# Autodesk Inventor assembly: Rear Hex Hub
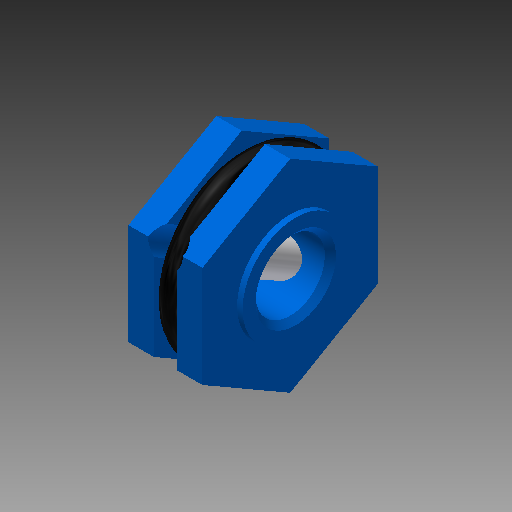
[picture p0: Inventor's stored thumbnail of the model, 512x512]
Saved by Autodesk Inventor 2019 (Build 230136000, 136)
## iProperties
Shininess: 50.0
Compacted: True
Length Units: 11272
Angle Units: 11279
Time Units: 11290
Mass Units: 11286
Length Display Precision: 4
Angle Display Precision: 2
Company: Autodesk
Created: 2000-05
Part Number: Rear Hex Hub
Project: Inventor Samples
User Status: IN PROGRESS
Description: ASSEMBLY - REAR HEX HUB
Document SubType Name: Assembly
Designer: The PD Team
Mass: 0.912527 g
Surface Area: 8.58066 cm^2
Volume: 0.552615 cm^3
Density: 1.65129 g/cm^3
Density: 0.0
Volumn: 0.0
Area: 0.0
PropertySet Name: Model Information
Control State: 0
Master: False
Checked Out: False
Checked Out Date: 2018-05-30
Last Check In Date: 2018-05-30
Author: The PD Team
Revision Number: A
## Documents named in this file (4)
- C:\Users\itools\Desktop\autodesk_inventor_2018_samples\Models\Assemblies\Suspension\Components\Rear Hex Hub.iam
- C:\Users\itools\Desktop\autodesk_inventor_2018_samples\Models\Assemblies\Suspension\Components\Hex Axle Pin.ipt
- C:\Users\itools\Desktop\autodesk_inventor_2018_samples\Models\Assemblies\Suspension\Components\Hex Retaining O-Ring.ipt
- C:\Users\itools\Desktop\autodesk_inventor_2018_samples\Models\Assemblies\Suspension\Components\Hex Drive.ipt
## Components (3 placed, 3 different names)
1. Hex Drive:1 — Mate:1, Mate:2, Mate:3, Mate:4
2. Axle Pin.ipt:1 — Mate:1, Mate:2
3. Hub Retaining Ring.ipt:1 — Mate:3, Mate:4
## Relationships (4: Mate 4)
- Mate:1: Hex Drive:1 ↔ Axle Pin.ipt:1
- Mate:2: Hex Drive:1 ↔ Axle Pin.ipt:1
- Mate:3: Hex Drive:1 ↔ Hub Retaining Ring.ipt:1
- Mate:4: Hex Drive:1 ↔ Hub Retaining Ring.ipt:1
## Named parameters: d0_d1 = 0, d1_d3 = 0
